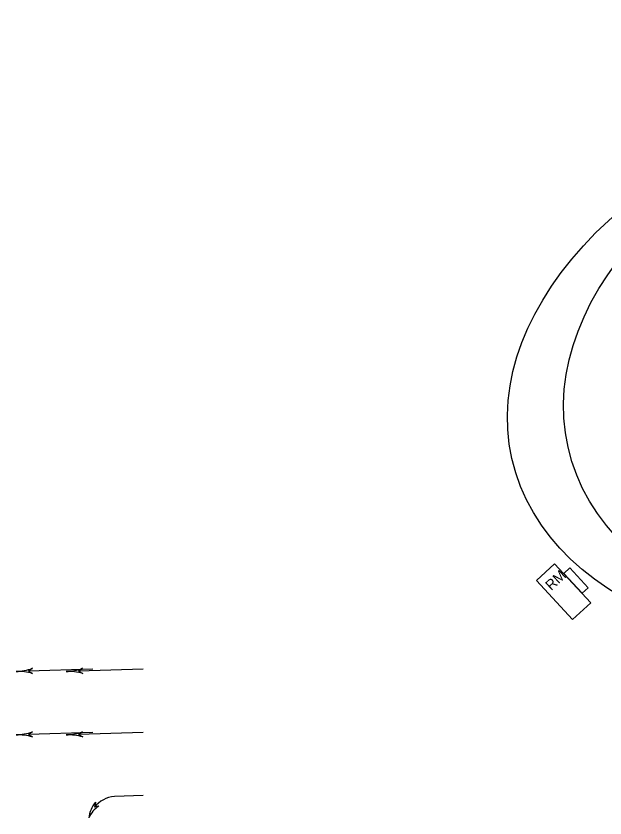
# Model space of a CAD drawing. Extents: x 596176 to 605330, y 332416 to 402398.
# Drawn here: x 604193.4 to 604308.1, y 339370.2 to 339526.2 of the extents above; entities that cross this region are included whole.
import ezdxf

# ---------------------------------------------------------------- set-up
doc = ezdxf.new("R2010")
doc.units = 0
doc.layers.add('P_LTG', color=7, linetype='Continuous')
doc.layers.add('P_SIG', color=7, linetype='Continuous')

# ---------------------------------------------------------------- blocks, each defined once
blk = doc.blocks.new('_U318')
at = {"layer": 'P_LTG'}
blk.add_ellipse((0.092, 25.117), major_axis=(0, 6.647), ratio=0.636439, dxfattribs=at)

msp = doc.modelspace()

# ---------------------------------------------------------------- linework, layer by layer
at = {"layer": 'P_SIG'}
for p, q in [((604208.36, 339399.14), (604195.79, 339398.75)), ((604218.13, 339399.14), (604205.56, 339398.75)), ((604208.36, 339386.78), (604195.79, 339386.39)), ((604218.13, 339386.78), (604205.56, 339386.39)), ((604218.13, 339374.5), (604212.54, 339374.33)), ((604208.87, 339373.21), (604208.66, 339372.26)), ((604209.55, 339372.47), (604208.66, 339372.26))]:
    msp.add_line(p, q, dxfattribs=at)
for points in [[(604305.31, 339412.06), (604298.27, 339419.64), (604294.74, 339416.36), (604301.78, 339408.78)], [(604301.25, 339418.83), (604300.08, 339417.74), (604303.67, 339413.88), (604304.84, 339414.97)]]:
    msp.add_lwpolyline(points, close=True, dxfattribs=at)
for points in [[(604196.58, 339399.28), (604195.79, 339398.75), (604196.61, 339398.28)], [(604206.35, 339399.28), (604205.56, 339398.75), (604206.38, 339398.28)], [(604196.58, 339386.92), (604195.79, 339386.39), (604196.61, 339385.92)], [(604206.35, 339386.92), (604205.56, 339386.39), (604206.38, 339385.92)]]:
    msp.add_lwpolyline(points, dxfattribs=at)
for centre, radius, start, end in [((604193.07, 339409.16), 10.49, 271.7654, 289.5278), ((604202.84, 339409.16), 10.49, 271.7654, 289.5278), ((604193.72, 339388.19), 10.49, 74.0031, 91.7654), ((604203.49, 339388.19), 10.49, 74.0031, 91.7654), ((604193.07, 339396.81), 10.49, 271.7654, 289.5278), ((604193.72, 339375.84), 10.49, 74.0031, 91.7654), ((604202.84, 339396.81), 10.49, 271.7654, 289.5278), ((604203.49, 339375.84), 10.49, 74.0031, 91.7654), ((604213.12, 339368.56), 5.8, 95.7307, 140.2946), ((604213.56, 339369.36), 6.07, 140.594, 172.4501), ((604212.26, 339368.11), 5.14, 121.8503, 156.4987)]:
    msp.add_arc(centre, radius, start, end, dxfattribs=at)

# ---------------------------------------------------------------- block references
at = {"layer": 'P_SIG', "xscale": 13.123333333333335, "yscale": 13.123333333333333, "rotation": 102.6891845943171}
for p in [(604707.83, 339532.72), (604696.9, 339530.5)]:
    msp.add_blockref('_U318', p, dxfattribs=at)

# ---------------------------------------------------------------- texts
at = {"layer": 'P_SIG'}
msp.add_text('RM', height=2, rotation=42.8976, dxfattribs=at).set_placement((604297.62, 339414.31))

doc.saveas('drawing.dxf')
